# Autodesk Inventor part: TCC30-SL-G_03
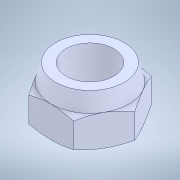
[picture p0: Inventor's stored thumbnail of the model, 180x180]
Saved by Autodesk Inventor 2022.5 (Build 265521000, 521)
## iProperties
Created: 2023-09
Part Number: TCC30-SL-G_03
Material: 一般
Document SubType Name: Modeling
Designer: ImaoCorp
Density: 1 g/cm^3
Appearance: 既定
Author: ImaoCorp
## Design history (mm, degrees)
feature "TCC30-SL-G_03"
node "ソリッド1"
